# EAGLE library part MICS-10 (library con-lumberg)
CONNECTOR
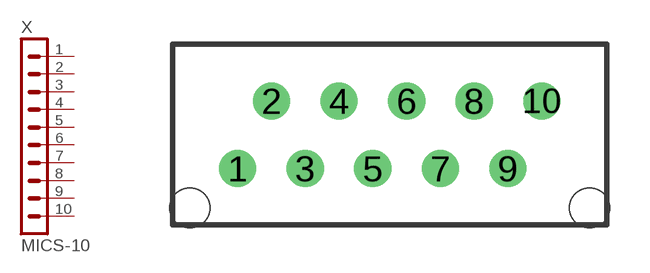
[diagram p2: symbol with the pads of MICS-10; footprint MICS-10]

Designator prefix X

## MICS-10 (OC_FARNELL: unknown; OC_NEWARK: unknown)  [MICS-10]
1  1  pas
2  2  pas
3  3  pas
4  4  pas
5  5  pas
6  6  pas
7  7  pas
8  8  pas
9  9  pas
10  10  pas

## Footprint MICS-10 (pad centres in mm)
CONNECTOR
drill 0.85 pad 1.397 round: 1 -5.715,-1.27; 2 -4.445,1.27; 3 -3.175,-1.27; 4 -1.905,1.27; 5 -0.635,-1.27; 6 0.635,1.27; 7 1.905,-1.27; 8 3.175,1.27; 9 4.445,-1.27; 10 5.715,1.27
hole 1.5 at 7.515,-2.75
hole 1.5 at -7.515,-2.75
